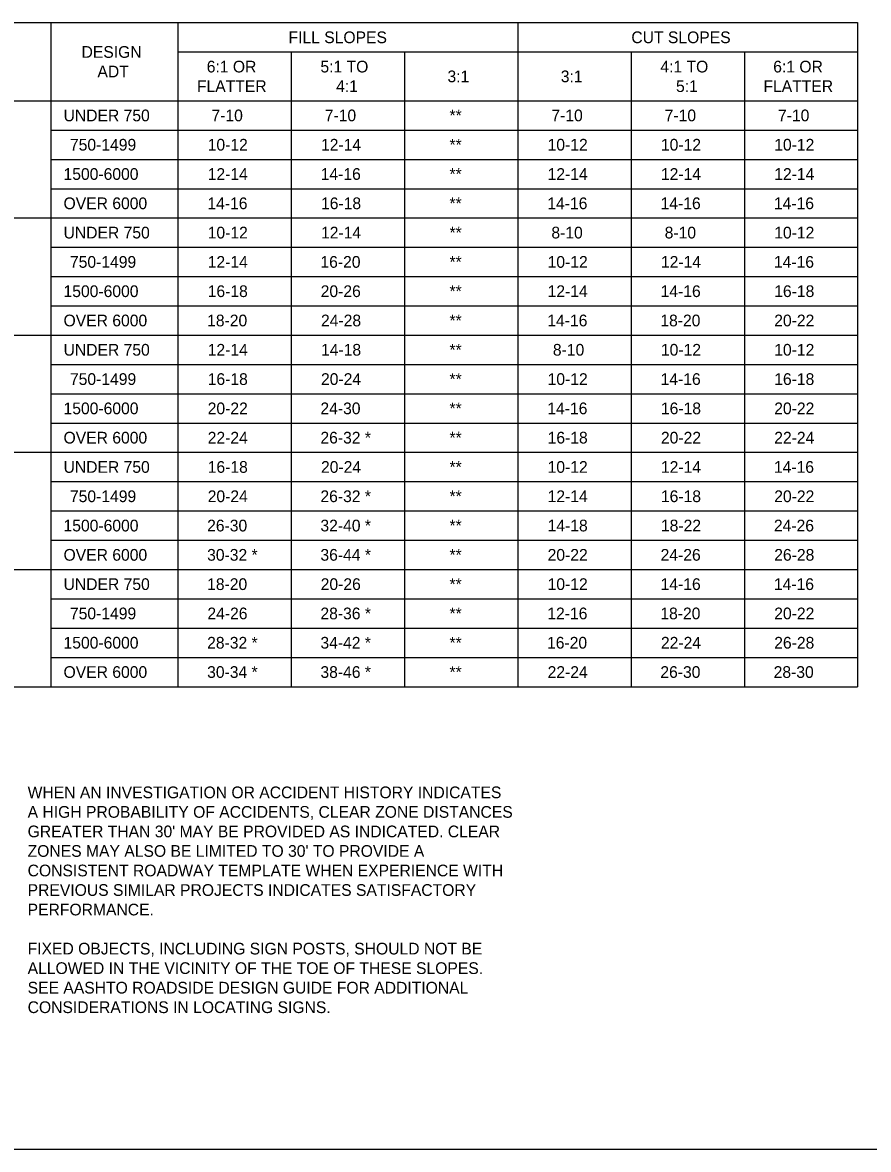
# Model space of a CAD drawing. Extents: x 49991.4 to 50021, y 49987.6 to 50011.4.
# Drawn here: x 50008.75 to 50013.08, y 49987.8 to 49993.57 of the extents above; entities that cross this region are included whole.
import ezdxf

# ---------------------------------------------------------------- set-up
doc = ezdxf.new("R2010")
doc.units = 0
doc.layers.add('Level 1', color=7, linetype='Continuous')
doc.layers.add('Level 2', color=7, linetype='Continuous')

msp = doc.modelspace()

# ---------------------------------------------------------------- linework, layer by layer
at = {"layer": 'Level 1'}
msp.add_lwpolyline([(49999.3835, 49998.9992), (50016.7501, 49998.9992), (50016.7501, 49987.7988), (49999.3835, 49987.7988)], close=True, dxfattribs=at)
at = {"layer": 'Level 2'}
for p, q in [((50008.2479, 49993.5684), (50013.0279, 49993.5684)), ((50008.8979, 49993.5684), (50008.8979, 49990.1684)), ((50009.5479, 49993.5684), (50009.5479, 49990.1684)), ((50011.2879, 49993.5684), (50011.2879, 49990.1684)), ((50013.0279, 49993.5684), (50013.0279, 49990.1684)), ((50008.8979, 49993.5434), (50008.8979, 49990.7084)), ((50009.5479, 49993.4184), (50013.0279, 49993.4184)), ((50010.1279, 49993.4184), (50010.1279, 49990.1684)), ((50010.7079, 49993.4184), (50010.7079, 49990.1684)), ((50011.8679, 49993.4184), (50011.8679, 49990.1684)), ((50012.4479, 49993.4184), (50012.4479, 49990.1684)), ((50008.2479, 49993.1684), (50013.0279, 49993.1684)), ((50008.8979, 49993.0184), (50013.0279, 49993.0184)), ((50008.8979, 49992.8684), (50013.0279, 49992.8684)), ((50008.8979, 49992.7184), (50013.0279, 49992.7184)), ((50008.2479, 49992.5684), (50013.0279, 49992.5684)), ((50008.8979, 49992.4184), (50013.0279, 49992.4184)), ((50008.8979, 49992.2684), (50013.0279, 49992.2684)), ((50008.8979, 49992.1184), (50013.0279, 49992.1184)), ((50008.2479, 49991.9684), (50013.0279, 49991.9684)), ((50008.8979, 49991.8184), (50013.0279, 49991.8184)), ((50008.8979, 49991.6684), (50013.0279, 49991.6684)), ((50008.8979, 49991.5184), (50013.0279, 49991.5184)), ((50008.2479, 49991.3684), (50013.0279, 49991.3684)), ((50008.8979, 49991.2184), (50013.0279, 49991.2184)), ((50008.8979, 49991.0684), (50013.0279, 49991.0684)), ((50008.8979, 49990.9184), (50013.0279, 49990.9184)), ((50008.2479, 49990.7684), (50013.0279, 49990.7684)), ((50008.8979, 49990.6184), (50013.0279, 49990.6184)), ((50008.8979, 49990.4684), (50013.0279, 49990.4684)), ((50008.8979, 49990.3184), (50013.0279, 49990.3184)), ((50008.2479, 49990.1684), (50013.0279, 49990.1684))]:
    msp.add_line(p, q, dxfattribs=at)

# ---------------------------------------------------------------- texts
for s, p in [('FILL SLOPES', (50010.1145, 49993.4634)), ('CUT SLOPES', (50011.8695, 49993.4634)), ('DESIGN', (50009.055, 49993.3884)), ('ADT', (50009.1364, 49993.2884)), ('6:1 OR', (50009.6959, 49993.3134)), ('5:1 TO', (50010.278, 49993.3134)), ('4:1 TO', (50012.018, 49993.3134)), ('6:1 OR', (50012.5958, 49993.3134)), ('FLATTER', (50009.6458, 49993.2134)), ('4:1', (50010.3582, 49993.2134)), ('3:1', (50010.9283, 49993.2634)), ('3:1', (50011.5083, 49993.2634)), ('5:1', (50012.0982, 49993.2134)), ('FLATTER', (50012.5457, 49993.2134)), ('UNDER 750', (50008.9629, 49993.0634)), (' 7-10', (50009.6979, 49993.0634)), (' 7-10', (50010.2779, 49993.0634)), ('**', (50010.9387, 49993.0634)), (' 7-10', (50011.4379, 49993.0634)), (' 7-10', (50012.0179, 49993.0634)), (' 7-10', (50012.5979, 49993.0634)), ('750-1499', (50008.9957, 49992.9134)), ('10-12', (50009.7009, 49992.9134)), ('12-14', (50010.2809, 49992.9134)), ('**', (50010.9387, 49992.9134)), ('10-12', (50011.4409, 49992.9134)), ('10-12', (50012.0209, 49992.9134)), ('10-12', (50012.6009, 49992.9134)), ('1500-6000', (50008.9629, 49992.7634)), ('12-14', (50009.7009, 49992.7634)), ('14-16', (50010.2793, 49992.7634)), ('**', (50010.9387, 49992.7634)), ('12-14', (50011.4409, 49992.7634)), ('12-14', (50012.0209, 49992.7634)), ('12-14', (50012.6009, 49992.7634)), ('OVER 6000', (50008.9629, 49992.6134)), ('14-16', (50009.6993, 49992.6134)), ('16-18', (50010.2809, 49992.6134)), ('**', (50010.9387, 49992.6134)), ('14-16', (50011.4393, 49992.6134)), ('14-16', (50012.0193, 49992.6134)), ('14-16', (50012.5993, 49992.6134)), ('UNDER 750', (50008.9629, 49992.4634)), ('10-12', (50009.7009, 49992.4634)), ('12-14', (50010.2809, 49992.4634)), ('**', (50010.9387, 49992.4634)), (' 8-10', (50011.4379, 49992.4634)), (' 8-10', (50012.0179, 49992.4634)), ('10-12', (50012.6009, 49992.4634)), ('750-1499', (50008.9957, 49992.3134)), ('12-14', (50009.7009, 49992.3134)), ('16-20', (50010.2779, 49992.3134)), ('**', (50010.9387, 49992.3134)), ('10-12', (50011.4409, 49992.3134)), ('12-14', (50012.0209, 49992.3134)), ('14-16', (50012.5993, 49992.3134)), ('1500-6000', (50008.9629, 49992.1634)), ('16-18', (50009.7009, 49992.1634)), ('20-26', (50010.2793, 49992.1634)), ('**', (50010.9387, 49992.1634)), ('12-14', (50011.4409, 49992.1634)), ('14-16', (50012.0193, 49992.1634)), ('16-18', (50012.6009, 49992.1634)), ('OVER 6000', (50008.9629, 49992.0134)), ('18-20', (50009.6979, 49992.0134)), ('24-28', (50010.2809, 49992.0134)), ('**', (50010.9387, 49992.0134)), ('14-16', (50011.4393, 49992.0134)), ('18-20', (50012.0179, 49992.0134)), ('20-22', (50012.6009, 49992.0134)), ('UNDER 750', (50008.9629, 49991.8634)), ('12-14', (50009.7009, 49991.8634)), ('14-18', (50010.2809, 49991.8634)), ('**', (50010.9387, 49991.8634)), ('8-10', (50011.4679, 49991.8634)), ('10-12', (50012.0209, 49991.8634)), ('10-12', (50012.6009, 49991.8634)), ('750-1499', (50008.9957, 49991.7134)), ('16-18', (50009.7009, 49991.7134)), ('20-24', (50010.2809, 49991.7134)), ('**', (50010.9387, 49991.7134)), ('10-12', (50011.4409, 49991.7134)), ('14-16', (50012.0193, 49991.7134)), ('16-18', (50012.6009, 49991.7134)), ('1500-6000', (50008.9629, 49991.5634)), ('20-22', (50009.7009, 49991.5634)), ('24-30', (50010.2779, 49991.5634)), ('24-30', (50010.2779, 49991.5634)), ('**', (50010.9387, 49991.5634)), ('14-16', (50011.4393, 49991.5634)), ('16-18', (50012.0209, 49991.5634)), ('20-22', (50012.6009, 49991.5634)), ('OVER 6000', (50008.9629, 49991.4134)), ('22-24', (50009.7009, 49991.4134)), ('26-32 *', (50010.2779, 49991.4134)), ('**', (50010.9387, 49991.4134)), ('16-18', (50011.4409, 49991.4134)), ('20-22', (50012.0209, 49991.4134)), ('22-24', (50012.6009, 49991.4134)), ('UNDER 750', (50008.9629, 49991.2634)), ('16-18', (50009.7009, 49991.2634)), ('20-24', (50010.2809, 49991.2634)), ('**', (50010.9387, 49991.2634)), ('10-12', (50011.4409, 49991.2634)), ('12-14', (50012.0209, 49991.2634)), ('14-16', (50012.5993, 49991.2634)), ('750-1499', (50008.9957, 49991.1134)), ('20-24', (50009.7009, 49991.1134)), ('26-32 *', (50010.2779, 49991.1134)), ('**', (50010.9387, 49991.1134)), ('12-14', (50011.4409, 49991.1134)), ('16-18', (50012.0209, 49991.1134)), ('20-22', (50012.6009, 49991.1134)), ('1500-6000', (50008.9629, 49990.9634)), ('26-30', (50009.6979, 49990.9634)), ('32-40 *', (50010.2779, 49990.9634)), ('**', (50010.9387, 49990.9634)), ('14-18', (50011.4409, 49990.9634)), ('18-22', (50012.0209, 49990.9634)), ('24-26', (50012.5993, 49990.9634)), ('OVER 6000', (50008.9629, 49990.8134)), ('30-32 *', (50009.6979, 49990.8134)), ('36-44 *', (50010.2779, 49990.8134)), ('**', (50010.9387, 49990.8134)), ('20-22', (50011.4409, 49990.8134)), ('24-26', (50012.0193, 49990.8134)), ('26-28', (50012.6009, 49990.8134)), ('UNDER 750', (50008.9629, 49990.6634)), ('18-20', (50009.6979, 49990.6634)), ('20-26', (50010.2793, 49990.6634)), ('**', (50010.9387, 49990.6634)), ('10-12', (50011.4409, 49990.6634)), ('14-16', (50012.0193, 49990.6634)), ('14-16', (50012.5993, 49990.6634)), ('750-1499', (50008.9957, 49990.5134)), ('24-26', (50009.6993, 49990.5134)), ('28-36 *', (50010.2779, 49990.5134)), ('**', (50010.9387, 49990.5134)), ('12-16', (50011.4393, 49990.5134)), ('18-20', (50012.0179, 49990.5134)), ('20-22', (50012.6009, 49990.5134)), ('1500-6000', (50008.9629, 49990.3634)), ('28-32 *', (50009.6979, 49990.3634)), ('34-42 *', (50010.2779, 49990.3634)), ('**', (50010.9387, 49990.3634)), ('16-20', (50011.4379, 49990.3634)), ('22-24', (50012.0209, 49990.3634)), ('26-28', (50012.6009, 49990.3634)), ('OVER 6000', (50008.9629, 49990.2134)), ('30-34 *', (50009.6979, 49990.2134)), ('38-46 *', (50010.2779, 49990.2134)), ('**', (50010.9387, 49990.2134)), ('22-24', (50011.4409, 49990.2134)), ('26-30', (50012.0179, 49990.2134)), ('28-30', (50012.5979, 49990.2134)), ('WHEN AN INVESTIGATION OR ACCIDENT HISTORY INDICATES', (50008.7791, 49989.5972)), ('A HIGH PROBABILITY OF ACCIDENTS, CLEAR ZONE DISTANCES', (50008.7791, 49989.4972)), ("GREATER THAN 30' MAY BE PROVIDED AS INDICATED. CLEAR", (50008.7791, 49989.3972)), ("ZONES MAY ALSO BE LIMITED TO 30' TO PROVIDE A", (50008.7791, 49989.2972)), ('CONSISTENT ROADWAY TEMPLATE WHEN EXPERIENCE WITH', (50008.7791, 49989.1972)), ('PREVIOUS SIMILAR PROJECTS INDICATES SATISFACTORY', (50008.7791, 49989.0972)), ('PERFORMANCE.', (50008.7791, 49988.9972)), ('FIXED OBJECTS, INCLUDING SIGN POSTS, SHOULD NOT BE', (50008.7791, 49988.7972)), ('ALLOWED IN THE VICINITY OF THE TOE OF THESE SLOPES.', (50008.7791, 49988.6972)), ('SEE AASHTO ROADSIDE DESIGN GUIDE FOR ADDITIONAL', (50008.7791, 49988.5972)), ('CONSIDERATIONS IN LOCATING SIGNS.', (50008.7791, 49988.4972))]:
    msp.add_text(s, height=0.06, dxfattribs=at).set_placement(p)

doc.saveas('drawing.dxf')
